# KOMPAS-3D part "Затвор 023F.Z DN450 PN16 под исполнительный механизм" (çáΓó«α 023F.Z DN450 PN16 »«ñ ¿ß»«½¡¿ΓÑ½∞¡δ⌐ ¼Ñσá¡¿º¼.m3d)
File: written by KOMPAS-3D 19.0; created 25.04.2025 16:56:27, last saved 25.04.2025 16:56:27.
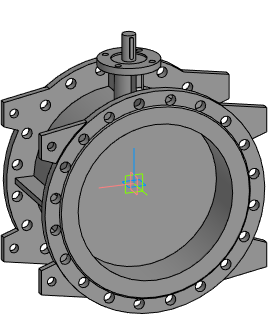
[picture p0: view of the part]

Document properties: Автор: Евгений; Полное имя файла: E:\Dendor Работа Сачек\3D для проекитирвщиков\1.7 Тип 023F.Z Затвор дисковый поворотный фланцевый с двумя эксцентриками\stp_Тип 023F.Z. Затвор под исполн. механизм\Затвор 023F.Z DN450 PN16 под исполнительный механизм.m3d

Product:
- Part/product: Затвор 023F.Z DN450 PN16 под исполнительный механизм

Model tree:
1. Операция без истории:1  (labels: Затвор 023F.Z DN450 PN16 под исполнительный механизм)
